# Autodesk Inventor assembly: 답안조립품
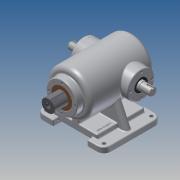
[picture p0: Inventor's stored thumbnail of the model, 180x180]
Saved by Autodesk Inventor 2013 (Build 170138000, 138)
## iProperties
Created: 2014-12
Part Number: 답안조립품
Document SubType Name: Assembly
Designer: CAD-B22
Mass: 8641.3 g
Surface Area: 4328.77 cm^2
Volume: 2314.18 cm^3
Density: 3.73407 g/cm^3
Author: CAD-B22
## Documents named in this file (13)
- C:\Users\CAD-B22\Desktop\341228V1003\답안조립품.iam
- C:\Users\CAD-B22\Desktop\341228V1003\본체.ipt
- C:\Users\CAD-B22\Desktop\341228V1003\M4x0.7.ipt
- C:\Users\CAD-B22\Desktop\341228V1003\베어링 6205.ipt
- 베어링 6205.ipt
- C:\Users\CAD-B22\Desktop\341228V1003\부시.ipt
- C:\Users\CAD-B22\Desktop\341228V1003\슬라이드 커버.ipt
- C:\Users\CAD-B22\Desktop\341228V1003\슬라이드.ipt
- C:\Users\CAD-B22\Desktop\341228V1003\오일실.ipt
- 오일실.ipt
- C:\Users\CAD-B22\Desktop\341228V1003\축 커버.ipt
- C:\Users\CAD-B22\Desktop\341228V1003\편심축.ipt
- C:\Users\CAD-B22\Desktop\341228V1003\스프링.ipt
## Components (12 placed, 1 different names)
1. M4x0.7:1 — 각도:1
2. M4x0.7:2
3. M4x0.7:3
4. M4x0.7:4
5. M4x0.7:5 — 각도:2
6. M4x0.7:6
7. M4x0.7:7
8. M4x0.7:8
9. M4x0.7:9 — 각도:3
10. M4x0.7:10
11. M4x0.7:11
12. M4x0.7:12
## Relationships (3: Angle 3)
- 각도:1 [Angle]: M4x0.7:1
- 각도:2 [Angle]: M4x0.7:5
- 각도:3 [Angle]: M4x0.7:9
